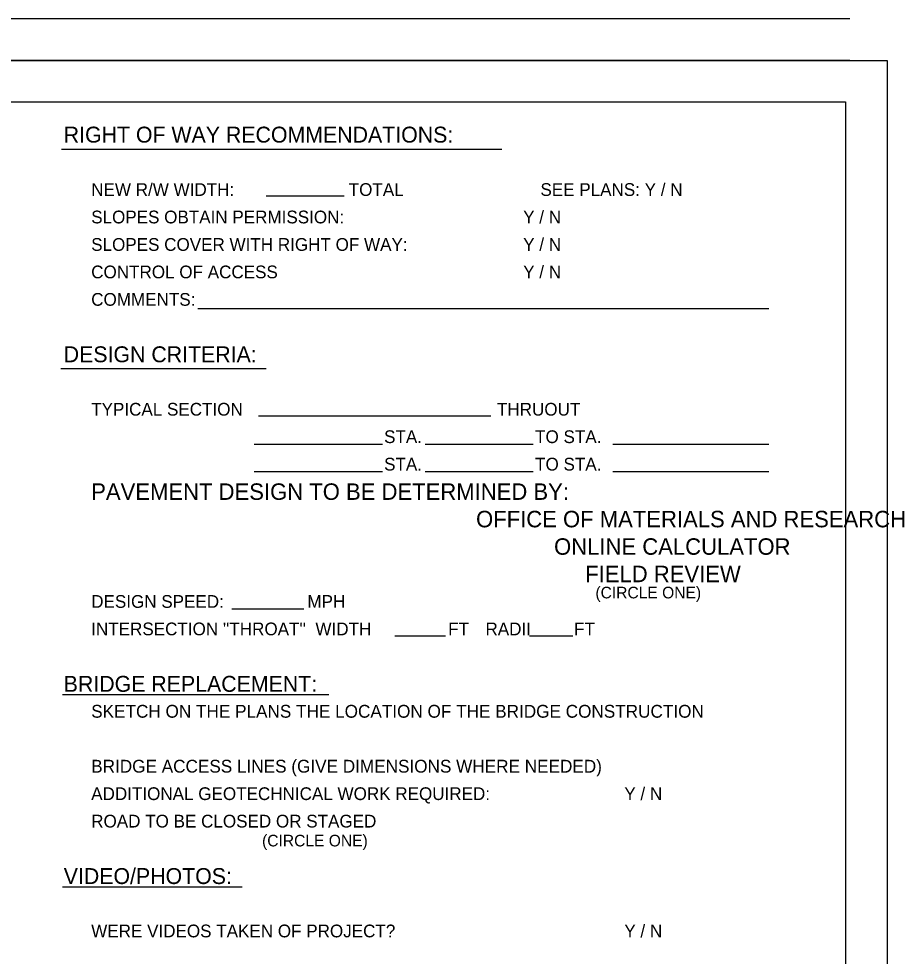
# Model space of a CAD drawing. Extents: x -796 to 2793, y -4650 to 4425.
# Drawn here: x 2261 to 2793, y 2712 to 3275 of the extents above; entities that cross this region are included whole.
import ezdxf

# ---------------------------------------------------------------- set-up
doc = ezdxf.new("R2010")
doc.units = 0
for name, color, linetype in [('RD_HC_CL', 7, 'Continuous'), ('RD_HC_Data', 7, 'Continuous'), ('RD_HC_Data_Tic', 7, 'Continuous')]:
    doc.layers.add(name, color=color, linetype=linetype)

msp = doc.modelspace()

# ---------------------------------------------------------------- linework, layer by layer
at = {"layer": 'RD_HC_CL'}
msp.add_lwpolyline([(986.45, 3250), (2782.44, 3250), (2782.44, 2150), (986.45, 2150)], close=True, dxfattribs=at)
at = {"layer": 'RD_HC_Data'}
for p, q in [((2760, 3275), (1000, 3275)), ((2760, 3275), (1000, 3275)), ((2760, 3250), (1000, 3250)), ((2286.6, 3196.61), (2550.96, 3196.61)), ((2409.44, 3168.54), (2456.33, 3168.54)), ((2368.45, 3100.95), (2711.43, 3100.95)), ((2286.31, 3064.91), (2299.16, 3064.91)), ((2286.31, 3064.91), (2409.44, 3064.91)), ((2405.03, 3036.32), (2544.39, 3036.32)), ((2402.36, 3019.44), (2479.33, 3019.44)), ((2505.08, 3019.44), (2569.96, 3019.44)), ((2617.79, 3019.44), (2711.43, 3019.44)), ((2402.36, 3002.94), (2479.33, 3002.94)), ((2505.08, 3002.94), (2569.96, 3002.94)), ((2617.79, 3002.94), (2711.43, 3002.94)), ((2388.9, 2920.38), (2432.17, 2920.38)), ((2486.84, 2904.24), (2517.25, 2904.24)), ((2567.71, 2904.24), (2593.73, 2904.24)), ((2287.25, 2868.98), (2447.08, 2868.98)), ((2287.25, 2753.48), (2395.04, 2753.48))]:
    msp.add_line(p, q, dxfattribs=at)
msp.add_lwpolyline([(1082.45, 3225), (2757.45, 3225), (2757.45, 2175), (1082.45, 2175)], close=True, dxfattribs=at)

# ---------------------------------------------------------------- texts
at = {"layer": 'RD_HC_Data_Tic'}
for s, height, p in [('RIGHT OF WAY RECOMMENDATIONS:', 9.5701, (2287.98, 3200.58)), ('NEW R/W WIDTH:', 7.6561, (2304.48, 3168.54)), ('TOTAL', 7.656, (2459.12, 3168.54)), ('SEE PLANS: Y / N', 7.6561, (2574.23, 3168.54)), ('SLOPES OBTAIN PERMISSION:', 7.6561, (2304.48, 3152.04)), (' Y / N', 7.656, (2561.03, 3152.04)), (' Y / N', 7.656, (2561.03, 3135.54)), ('SLOPES COVER WITH RIGHT OF WAY:', 7.6561, (2304.48, 3135.54)), ('CONTROL OF ACCESS', 7.6561, (2304.48, 3119.03)), (' Y / N', 7.656, (2561.03, 3119.03)), ('COMMENTS:', 7.656, (2304.48, 3102.53)), ('DESIGN CRITERIA:', 9.5701, (2287.98, 3068.58)), ('TYPICAL SECTION', 7.6561, (2304.48, 3036.53)), ('THRUOUT', 7.656, (2548.14, 3036.53)), ('STA.', 7.656, (2480.35, 3020.03)), ('TO STA.', 7.656, (2571.03, 3020.03)), ('STA.', 7.656, (2480.35, 3003.53)), ('TO STA.', 7.656, (2571.03, 3003.53)), ('PAVEMENT DESIGN TO BE DETERMINED BY:', 9.9001, (2304.48, 2985.91)), ('OFFICE OF MATERIALS AND RESEARCH', 9.9001, (2535.57, 2969.41)), ('ONLINE CALCULATOR', 9.9001, (2582.42, 2952.91)), ('FIELD REVIEW', 9.9001, (2601.11, 2936.44)), ('(CIRCLE ONE)', 7.0001, (2607.25, 2926.7)), ('DESIGN SPEED:', 7.6561, (2304.48, 2921.03)), ('MPH', 7.656, (2434.29, 2921.03)), ("INTERSECTION ''THROAT''  WIDTH", 7.6561, (2304.48, 2904.53)), ('FT', 7.656, (2518.82, 2904.53)), ('RADII', 7.656, (2541.23, 2904.53)), ('FT', 7.656, (2594.43, 2904.53)), ('BRIDGE REPLACEMENT:', 9.5701, (2287.98, 2870.57)), ('SKETCH ON THE PLANS THE LOCATION OF THE BRIDGE CONSTRUCTION  ', 7.7001, (2304.48, 2855.01)), ('BRIDGE ACCESS LINES (GIVE DIMENSIONS WHERE NEEDED)', 7.7001, (2304.48, 2822.01)), ('ADDITIONAL GEOTECHNICAL WORK REQUIRED:', 7.6561, (2304.48, 2805.53)), ('Y / N', 7.656, (2624.61, 2805.53)), ('ROAD TO BE CLOSED OR STAGED', 7.6561, (2304.48, 2789.03)), ('(CIRCLE ONE)', 7.0001, (2407.08, 2777.66)), ('VIDEO/PHOTOS:', 9.5701, (2287.98, 2755.07)), ('WERE VIDEOS TAKEN OF PROJECT?', 7.6561, (2304.48, 2723.03)), ('Y / N', 7.656, (2624.61, 2723.03))]:
    msp.add_text(s, height=height, dxfattribs=at).set_placement(p)

doc.saveas('drawing.dxf')
